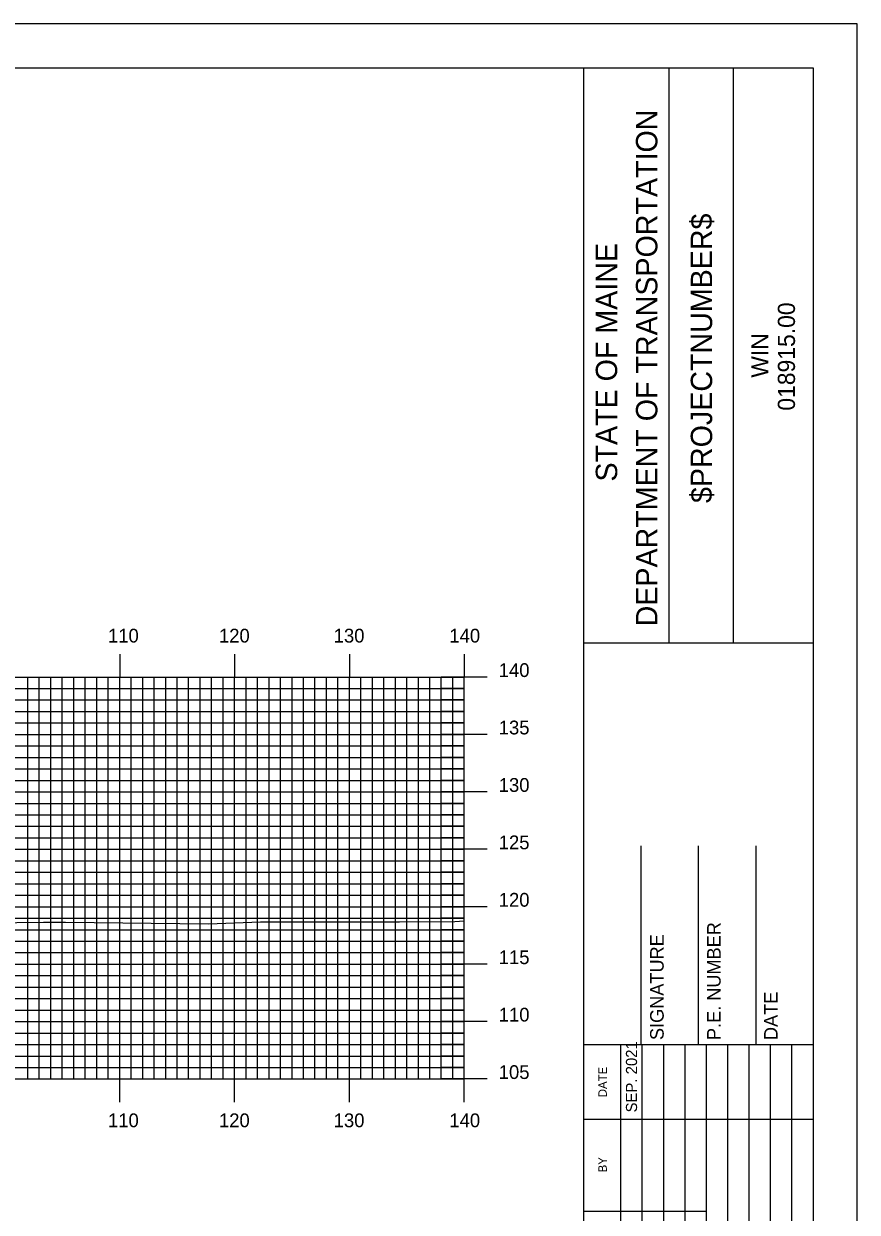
# Model space of a CAD drawing. Extents: x 1788943 to 1789287, y 442591 to 442811.
# Drawn here: x 1789210.8 to 1789283.4, y 442707.1 to 442810.5 of the extents above; entities that cross this region are included whole.
import ezdxf

# ---------------------------------------------------------------- set-up
doc = ezdxf.new("R2010")
doc.units = 0
for name, color, linetype in [('BORDER', 7, 'Continuous'), ('H_V ANNOTATION', 7, 'Continuous'), ('MAJOR', 7, 'Continuous'), ('MINOR', 7, 'Continuous'), ('PLOT BOUNDARY', 7, 'Continuous'), ('S_Roadway_Centerline', 7, 'Continuous')]:
    doc.layers.add(name, color=color, linetype=linetype)

msp = doc.modelspace()

# ---------------------------------------------------------------- linework, layer by layer
at = {"layer": 'BORDER'}
for p, q in [((1789259.56, 442596.67), (1789259.56, 442806.67)), ((1789267.01, 442756.66), (1789267.01, 442806.66)), ((1789272.6, 442756.66), (1789272.6, 442806.66)), ((1789259.56, 442756.65), (1789279.56, 442756.65)), ((1789264.56, 442721.67), (1789264.56, 442738.97)), ((1789269.56, 442721.67), (1789269.56, 442738.97)), ((1789274.56, 442721.67), (1789274.56, 442738.97)), ((1789259.56, 442721.67), (1789279.56, 442721.67))]:
    msp.add_line(p, q, dxfattribs=at)
msp.add_lwpolyline([(1788959.56, 442596.67), (1789279.56, 442596.67), (1789279.56, 442806.67), (1788959.56, 442806.67)], close=True, dxfattribs=at)
for points in [[(1789262.79, 442715.17), (1789262.79, 442721.67)], [(1789264.65, 442686.68), (1789264.65, 442721.67)], [(1789266.51, 442721.67), (1789266.51, 442686.68)], [(1789268.38, 442686.68), (1789268.38, 442721.67)], [(1789270.24, 442686.68), (1789270.24, 442721.67)], [(1789272.1, 442686.68), (1789272.1, 442721.67)], [(1789273.97, 442686.68), (1789273.97, 442721.67)], [(1789275.83, 442686.68), (1789275.83, 442721.67)], [(1789277.69, 442686.68), (1789277.69, 442721.67)], [(1789262.79, 442686.68), (1789262.79, 442720.26)], [(1789259.56, 442715.17), (1789279.56, 442715.17)], [(1789259.56, 442707.17), (1789262.79, 442707.17)], [(1789262.79, 442707.17), (1789270.24, 442707.17)]]:
    msp.add_lwpolyline(points, dxfattribs=at)
at = {"layer": 'MAJOR'}
for p, q in [((1789219.16, 442755.67), (1789219.16, 442753.67)), ((1789229.16, 442755.67), (1789229.16, 442753.67)), ((1789239.16, 442755.67), (1789239.16, 442753.67)), ((1789249.16, 442755.67), (1789249.16, 442753.67)), ((1788969.16, 442753.67), (1789249.16, 442753.67)), ((1788969.16, 442753.67), (1789249.16, 442753.67)), ((1789219.16, 442718.67), (1789219.16, 442753.67)), ((1789229.16, 442718.67), (1789229.16, 442753.67)), ((1789239.16, 442718.67), (1789239.16, 442753.67)), ((1789251.16, 442753.67), (1789247.15, 442753.67)), ((1789249.16, 442718.67), (1789249.16, 442753.67)), ((1789249.16, 442718.67), (1789249.16, 442753.67)), ((1788969.16, 442748.67), (1789249.16, 442748.67)), ((1789251.16, 442748.67), (1789247.15, 442748.67)), ((1788969.16, 442743.67), (1789249.16, 442743.67)), ((1789251.16, 442743.67), (1789247.15, 442743.67)), ((1788969.16, 442738.67), (1789249.16, 442738.67)), ((1789251.16, 442738.67), (1789247.15, 442738.67)), ((1788969.16, 442733.67), (1789249.16, 442733.67)), ((1789251.16, 442733.67), (1789247.15, 442733.67)), ((1788969.16, 442728.67), (1789249.16, 442728.67)), ((1789251.16, 442728.67), (1789247.15, 442728.67)), ((1788969.16, 442723.67), (1789249.16, 442723.67)), ((1789251.16, 442723.67), (1789247.15, 442723.67)), ((1788969.16, 442718.67), (1789249.16, 442718.67)), ((1788969.16, 442718.67), (1789249.16, 442718.67)), ((1789219.16, 442716.66), (1789219.16, 442718.67)), ((1789229.16, 442716.66), (1789229.16, 442718.67)), ((1789239.16, 442716.66), (1789239.16, 442718.67)), ((1789251.16, 442718.67), (1789247.15, 442718.67)), ((1789249.16, 442716.66), (1789249.16, 442718.67))]:
    msp.add_line(p, q, dxfattribs=at)
at = {"layer": 'MINOR'}
for p, q in [((1789211.16, 442718.67), (1789211.16, 442753.67)), ((1789212.16, 442718.67), (1789212.16, 442753.67)), ((1789213.16, 442718.67), (1789213.16, 442753.67)), ((1789214.16, 442718.67), (1789214.16, 442753.67)), ((1789215.16, 442718.67), (1789215.16, 442753.67)), ((1789216.16, 442718.67), (1789216.16, 442753.67)), ((1789217.16, 442718.67), (1789217.16, 442753.67)), ((1789218.16, 442718.67), (1789218.16, 442753.67)), ((1789220.16, 442718.67), (1789220.16, 442753.67)), ((1789221.16, 442718.67), (1789221.16, 442753.67)), ((1789222.16, 442718.67), (1789222.16, 442753.67)), ((1789223.16, 442718.67), (1789223.16, 442753.67)), ((1789224.16, 442718.67), (1789224.16, 442753.67)), ((1789225.16, 442718.67), (1789225.16, 442753.67)), ((1789226.16, 442718.67), (1789226.16, 442753.67)), ((1789227.16, 442718.67), (1789227.16, 442753.67)), ((1789228.16, 442718.67), (1789228.16, 442753.67)), ((1789230.16, 442718.67), (1789230.16, 442753.67)), ((1789231.16, 442718.67), (1789231.16, 442753.67)), ((1789232.16, 442718.67), (1789232.16, 442753.67)), ((1789233.16, 442718.67), (1789233.16, 442753.67)), ((1789234.16, 442718.67), (1789234.16, 442753.67)), ((1789235.16, 442718.67), (1789235.16, 442753.67)), ((1789236.16, 442718.67), (1789236.16, 442753.67)), ((1789237.16, 442718.67), (1789237.16, 442753.67)), ((1789238.16, 442718.67), (1789238.16, 442753.67)), ((1789240.16, 442718.67), (1789240.16, 442753.67)), ((1789241.16, 442718.67), (1789241.16, 442753.67)), ((1789242.16, 442718.67), (1789242.16, 442753.67)), ((1789243.16, 442718.67), (1789243.16, 442753.67)), ((1789244.16, 442718.67), (1789244.16, 442753.67)), ((1789245.16, 442718.67), (1789245.16, 442753.67)), ((1789246.16, 442718.67), (1789246.16, 442753.67)), ((1789247.16, 442718.67), (1789247.16, 442753.67)), ((1789248.16, 442718.67), (1789248.16, 442753.67)), ((1788969.16, 442752.67), (1789249.16, 442752.67)), ((1789249.16, 442752.67), (1789247.15, 442752.67)), ((1788969.16, 442751.67), (1789249.16, 442751.67)), ((1789249.16, 442751.67), (1789247.15, 442751.67)), ((1788969.16, 442750.67), (1789249.16, 442750.67)), ((1789249.16, 442750.67), (1789247.15, 442750.67)), ((1788969.16, 442749.67), (1789249.16, 442749.67)), ((1789249.16, 442749.67), (1789247.15, 442749.67)), ((1788969.16, 442747.67), (1789249.16, 442747.67)), ((1789249.16, 442747.67), (1789247.15, 442747.67)), ((1788969.16, 442746.67), (1789249.16, 442746.67)), ((1789249.16, 442746.67), (1789247.15, 442746.67)), ((1788969.16, 442745.67), (1789249.16, 442745.67)), ((1789249.16, 442745.67), (1789247.15, 442745.67)), ((1788969.16, 442744.67), (1789249.16, 442744.67)), ((1789249.16, 442744.67), (1789247.15, 442744.67)), ((1788969.16, 442742.67), (1789249.16, 442742.67)), ((1788969.16, 442741.67), (1789249.16, 442741.67)), ((1789249.16, 442742.67), (1789247.15, 442742.67)), ((1789249.16, 442741.67), (1789247.15, 442741.67)), ((1788969.16, 442740.67), (1789249.16, 442740.67)), ((1789249.16, 442740.67), (1789247.15, 442740.67)), ((1788969.16, 442739.67), (1789249.16, 442739.67)), ((1789249.16, 442739.67), (1789247.15, 442739.67)), ((1788969.16, 442737.67), (1789249.16, 442737.67)), ((1789249.16, 442737.67), (1789247.15, 442737.67)), ((1788969.16, 442736.67), (1789249.16, 442736.67)), ((1789249.16, 442736.67), (1789247.15, 442736.67)), ((1788969.16, 442735.67), (1789249.16, 442735.67)), ((1789249.16, 442735.67), (1789247.15, 442735.67)), ((1788969.16, 442734.67), (1789249.16, 442734.67)), ((1789249.16, 442734.67), (1789247.15, 442734.67)), ((1788969.16, 442732.67), (1789249.16, 442732.67)), ((1789249.16, 442732.67), (1789247.15, 442732.67)), ((1788969.16, 442731.67), (1789249.16, 442731.67)), ((1789249.16, 442731.67), (1789247.15, 442731.67)), ((1788969.16, 442730.67), (1789249.16, 442730.67)), ((1789249.16, 442730.67), (1789247.15, 442730.67)), ((1788969.16, 442729.67), (1789249.16, 442729.67)), ((1789249.16, 442729.67), (1789247.15, 442729.67)), ((1788969.16, 442727.67), (1789249.16, 442727.67)), ((1789249.16, 442727.67), (1789247.15, 442727.67)), ((1788969.16, 442726.67), (1789249.16, 442726.67)), ((1789249.16, 442726.67), (1789247.15, 442726.67)), ((1788969.16, 442725.67), (1789249.16, 442725.67)), ((1789249.16, 442725.67), (1789247.15, 442725.67)), ((1788969.16, 442724.67), (1789249.16, 442724.67)), ((1789249.16, 442724.67), (1789247.15, 442724.67)), ((1788969.16, 442722.67), (1789249.16, 442722.67)), ((1789249.16, 442722.67), (1789247.15, 442722.67)), ((1788969.16, 442721.67), (1789249.16, 442721.67)), ((1789249.16, 442721.67), (1789247.15, 442721.67)), ((1788969.16, 442720.67), (1789249.16, 442720.67)), ((1789249.16, 442720.67), (1789247.15, 442720.67)), ((1788969.16, 442719.67), (1789249.16, 442719.67)), ((1789249.16, 442719.67), (1789247.15, 442719.67))]:
    msp.add_line(p, q, dxfattribs=at)
at = {"layer": 'PLOT BOUNDARY'}
msp.add_lwpolyline([(1788943.37, 442590.55), (1789283.37, 442590.55), (1789283.37, 442810.55), (1788943.37, 442810.55)], close=True, dxfattribs=at)
at = {"layer": 'S_Roadway_Centerline'}
msp.add_lwpolyline([(1789058.67, 442730.42), (1789075.08, 442730.42), (1789083.96, 442730.35), (1789106.02, 442730.5), (1789115.41, 442730.47), (1789119.82, 442730.49), (1789127.86, 442730.52), (1789139.1, 442730.93), (1789152.79, 442731.01), (1789158.05, 442730.98), (1789178.97, 442731.63), (1789194.44, 442731.95), (1789210.21, 442732.29), (1789212.51, 442732.32), (1789214.43, 442732.33), (1789226.88, 442732.18), (1789231.43, 442732.35), (1789243.52, 442732.36), (1789248.35, 442732.39), (1789249.16, 442732.43)], dxfattribs=at)

# ---------------------------------------------------------------- texts
at = {"layer": 'BORDER'}
for s, height, p in [('DEPARTMENT OF TRANSPORTATION', 1.8635, (1789265.97, 442758.08)), ('$PROJECTNUMBER$', 1.8635, (1789270.74, 442768.82)), ('STATE OF MAINE', 1.8635, (1789262.47, 442770.69)), ('018915.00', 1.491, (1789277.95, 442776.86)), ('WIN', 1.491, (1789275.63, 442779.73)), ('P.E. NUMBER', 1.1811, (1789271.48, 442722.06)), ('SIGNATURE', 1.181, (1789266.52, 442722.06)), ('DATE', 1.181, (1789276.44, 442722.06)), ('SEP. 2021', 0.969, (1789264.2, 442715.76)), ('DATE', 0.743, (1789261.57, 442717.08)), ('BY', 0.743, (1789261.57, 442710.54))]:
    msp.add_text(s, height=height, rotation=90, dxfattribs=at).set_placement(p)
at = {"layer": 'H_V ANNOTATION'}
for s, p in [('110', (1789218.14, 442756.67)), ('120', (1789227.8, 442756.67)), ('130', (1789237.79, 442756.67)), ('140', (1789247.86, 442756.67)), ('140', (1789252.16, 442753.67)), ('135', (1789252.16, 442748.67)), ('130', (1789252.16, 442743.67)), ('125', (1789252.16, 442738.67)), ('120', (1789252.16, 442733.67)), ('115', (1789252.16, 442728.67)), ('110', (1789252.16, 442723.67)), ('105', (1789252.16, 442718.67)), ('110', (1789218.14, 442714.47)), ('120', (1789227.8, 442714.47)), ('130', (1789237.79, 442714.47)), ('140', (1789247.86, 442714.47))]:
    msp.add_text(s, height=1.2, dxfattribs=at).set_placement(p)

doc.saveas('drawing.dxf')
